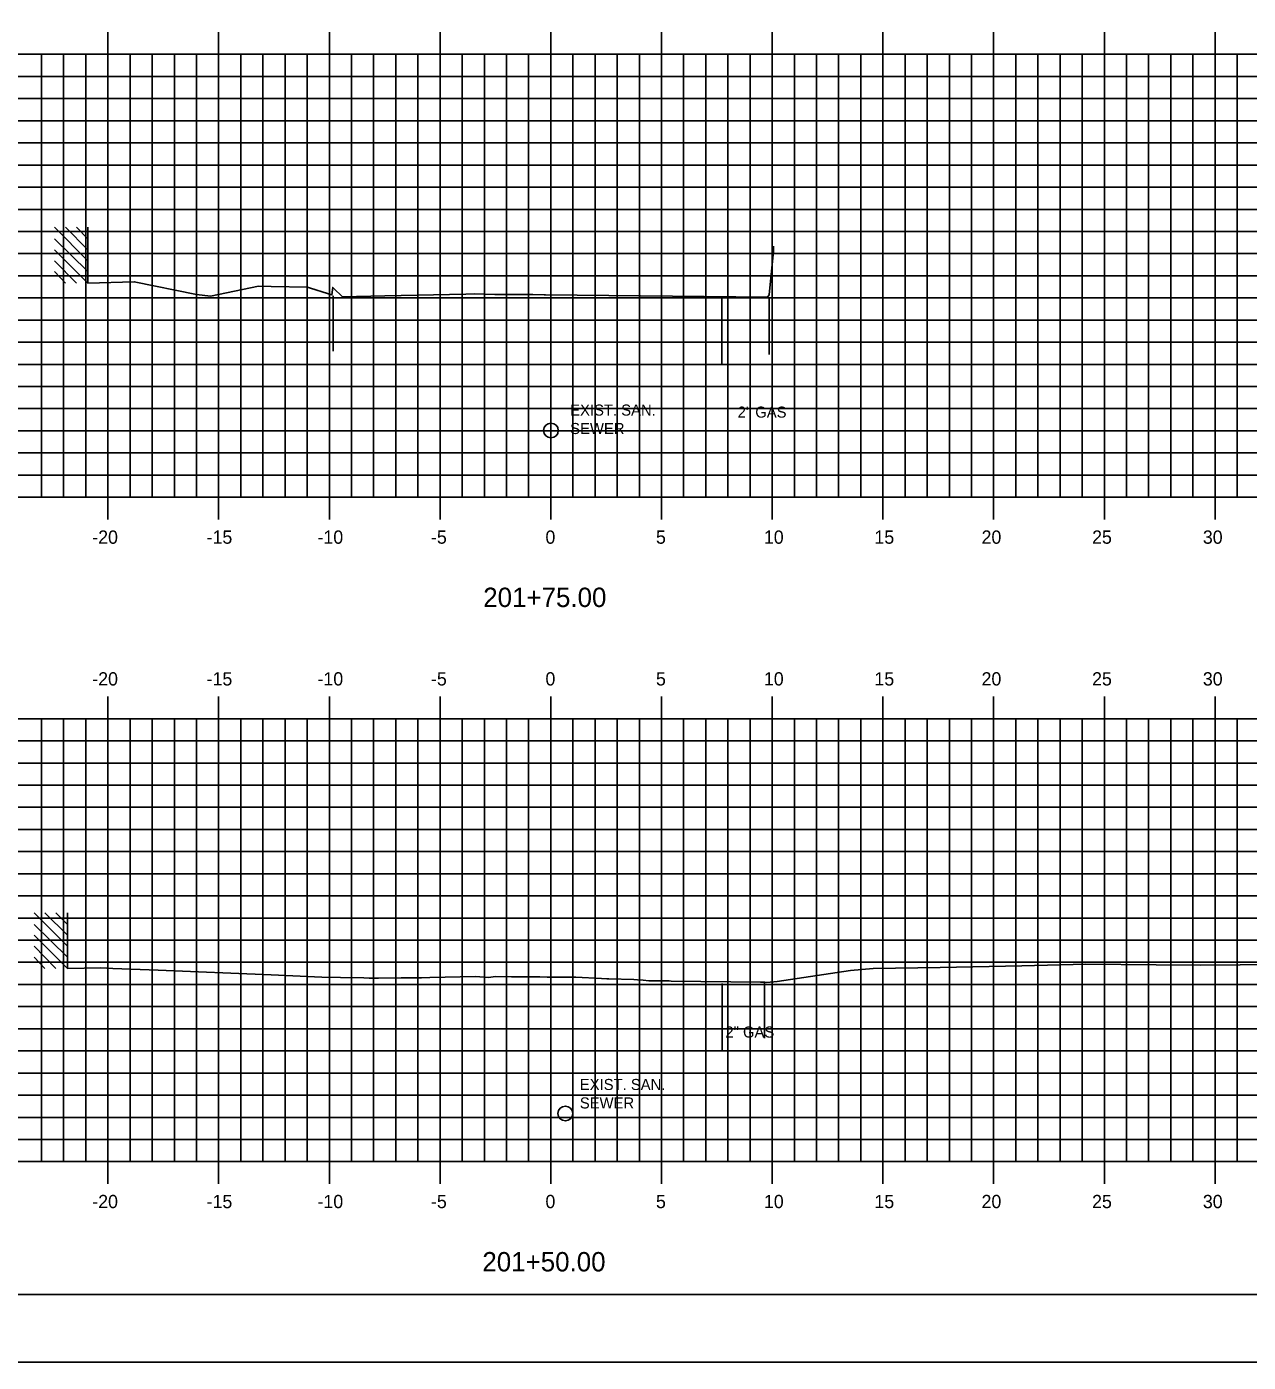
# Model space of a CAD drawing. Extents: x 1023905 to 1024075, y 394697 to 394807.
# Drawn here: x 1023964 to 1024019.2, y 394696.5 to 394756.9 of the extents above; entities that cross this region are included whole.
import ezdxf

# ---------------------------------------------------------------- set-up
doc = ezdxf.new("R2010")
doc.units = 0
for name, color, linetype in [('BORDER', 7, 'Continuous'), ('D_Text_Monospaced', 7, 'Continuous'), ('H_V ANNOTATION', 7, 'Continuous'), ('MAJOR', 7, 'Continuous'), ('MINOR', 7, 'Continuous'), ('PLOT BOUNDARY', 7, 'Continuous'), ('S_Buildings_SillElevation', 7, 'Continuous'), ('S_Roadway_Centerline', 7, 'Continuous'), ('S_Roadway_Edge_Pavement', 7, 'Continuous'), ('S_Utilities_UG_Gas_Line', 7, 'Continuous'), ('S_Utilities_UG_Sanitary_Sewer', 7, 'Continuous')]:
    doc.layers.add(name, color=color, linetype=linetype)

msp = doc.modelspace()

# ---------------------------------------------------------------- linework, layer by layer
at = {"layer": 'BORDER'}
msp.add_line((1023912.667, 394699.607), (1024072.667, 394699.607), dxfattribs=at)
at = {"layer": 'MAJOR'}
for p, q in [((1023967.667, 394756.609), (1023967.667, 394755.607)), ((1023972.667, 394756.609), (1023972.667, 394755.607)), ((1023977.667, 394756.609), (1023977.667, 394755.607)), ((1023982.667, 394756.609), (1023982.667, 394755.607)), ((1023987.667, 394756.609), (1023987.667, 394755.607)), ((1023992.667, 394756.609), (1023992.667, 394755.607)), ((1023997.667, 394756.609), (1023997.667, 394755.607)), ((1024002.667, 394756.609), (1024002.667, 394755.607)), ((1024007.667, 394756.609), (1024007.667, 394755.607)), ((1024012.667, 394756.609), (1024012.667, 394755.607)), ((1024017.667, 394756.609), (1024017.667, 394755.607)), ((1023917.667, 394755.607), (1024057.667, 394755.607)), ((1023967.667, 394735.607), (1023967.667, 394755.607)), ((1023972.667, 394735.607), (1023972.667, 394755.607)), ((1023977.667, 394735.607), (1023977.667, 394755.607)), ((1023982.667, 394735.607), (1023982.667, 394755.607)), ((1023987.667, 394735.607), (1023987.667, 394755.607)), ((1023992.667, 394735.607), (1023992.667, 394755.607)), ((1023997.667, 394735.607), (1023997.667, 394755.607)), ((1024002.667, 394735.607), (1024002.667, 394755.607)), ((1024007.667, 394735.607), (1024007.667, 394755.607)), ((1024012.667, 394735.607), (1024012.667, 394755.607)), ((1024017.667, 394735.607), (1024017.667, 394755.607)), ((1023917.667, 394750.607), (1024057.667, 394750.607)), ((1023917.667, 394745.607), (1024057.667, 394745.607)), ((1023917.667, 394740.607), (1024057.667, 394740.607)), ((1023917.667, 394735.607), (1024057.667, 394735.607)), ((1023967.667, 394734.605), (1023967.667, 394735.607)), ((1023972.667, 394734.605), (1023972.667, 394735.607)), ((1023977.667, 394734.605), (1023977.667, 394735.607)), ((1023982.667, 394734.605), (1023982.667, 394735.607)), ((1023987.667, 394734.605), (1023987.667, 394735.607)), ((1023992.667, 394734.605), (1023992.667, 394735.607)), ((1023997.667, 394734.605), (1023997.667, 394735.607)), ((1024002.667, 394734.605), (1024002.667, 394735.607)), ((1024007.667, 394734.605), (1024007.667, 394735.607)), ((1024012.667, 394734.605), (1024012.667, 394735.607)), ((1024017.667, 394734.605), (1024017.667, 394735.607)), ((1023967.667, 394726.609), (1023967.667, 394725.607)), ((1023972.667, 394726.609), (1023972.667, 394725.607)), ((1023977.667, 394726.609), (1023977.667, 394725.607)), ((1023982.667, 394726.609), (1023982.667, 394725.607)), ((1023987.667, 394726.609), (1023987.667, 394725.607)), ((1023992.667, 394726.609), (1023992.667, 394725.607)), ((1023997.667, 394726.609), (1023997.667, 394725.607)), ((1024002.667, 394726.609), (1024002.667, 394725.607)), ((1024007.667, 394726.609), (1024007.667, 394725.607)), ((1024012.667, 394726.609), (1024012.667, 394725.607)), ((1024017.667, 394726.609), (1024017.667, 394725.607)), ((1023917.667, 394725.607), (1024057.667, 394725.607)), ((1023967.667, 394705.607), (1023967.667, 394725.607)), ((1023972.667, 394705.607), (1023972.667, 394725.607)), ((1023977.667, 394705.607), (1023977.667, 394725.607)), ((1023982.667, 394705.607), (1023982.667, 394725.607)), ((1023987.667, 394705.607), (1023987.667, 394725.607)), ((1023992.667, 394705.607), (1023992.667, 394725.607)), ((1023997.667, 394705.607), (1023997.667, 394725.607)), ((1024002.667, 394705.607), (1024002.667, 394725.607)), ((1024007.667, 394705.607), (1024007.667, 394725.607)), ((1024012.667, 394705.607), (1024012.667, 394725.607)), ((1024017.667, 394705.607), (1024017.667, 394725.607)), ((1023917.667, 394720.607), (1024057.667, 394720.607)), ((1023917.667, 394715.607), (1024057.667, 394715.607)), ((1023917.667, 394710.607), (1024057.667, 394710.607)), ((1023917.667, 394705.607), (1024057.667, 394705.607)), ((1023967.667, 394704.605), (1023967.667, 394705.607)), ((1023972.667, 394704.605), (1023972.667, 394705.607)), ((1023977.667, 394704.605), (1023977.667, 394705.607)), ((1023982.667, 394704.605), (1023982.667, 394705.607)), ((1023987.667, 394704.605), (1023987.667, 394705.607)), ((1023992.667, 394704.605), (1023992.667, 394705.607)), ((1023997.667, 394704.605), (1023997.667, 394705.607)), ((1024002.667, 394704.605), (1024002.667, 394705.607)), ((1024007.667, 394704.605), (1024007.667, 394705.607)), ((1024012.667, 394704.605), (1024012.667, 394705.607)), ((1024017.667, 394704.605), (1024017.667, 394705.607))]:
    msp.add_line(p, q, dxfattribs=at)
at = {"layer": 'MINOR'}
for p, q in [((1023964.667, 394735.607), (1023964.667, 394755.607)), ((1023965.667, 394735.607), (1023965.667, 394755.607)), ((1023966.667, 394735.607), (1023966.667, 394755.607)), ((1023968.667, 394735.607), (1023968.667, 394755.607)), ((1023969.667, 394735.607), (1023969.667, 394755.607)), ((1023970.667, 394735.607), (1023970.667, 394755.607)), ((1023971.667, 394735.607), (1023971.667, 394755.607)), ((1023973.667, 394735.607), (1023973.667, 394755.607)), ((1023974.667, 394735.607), (1023974.667, 394755.607)), ((1023975.667, 394735.607), (1023975.667, 394755.607)), ((1023976.667, 394735.607), (1023976.667, 394755.607)), ((1023978.667, 394735.607), (1023978.667, 394755.607)), ((1023979.667, 394735.607), (1023979.667, 394755.607)), ((1023980.667, 394735.607), (1023980.667, 394755.607)), ((1023981.667, 394735.607), (1023981.667, 394755.607)), ((1023983.667, 394735.607), (1023983.667, 394755.607)), ((1023984.667, 394735.607), (1023984.667, 394755.607)), ((1023985.667, 394735.607), (1023985.667, 394755.607)), ((1023986.667, 394735.607), (1023986.667, 394755.607)), ((1023988.667, 394735.607), (1023988.667, 394755.607)), ((1023989.667, 394735.607), (1023989.667, 394755.607)), ((1023990.667, 394735.607), (1023990.667, 394755.607)), ((1023991.667, 394735.607), (1023991.667, 394755.607)), ((1023993.667, 394735.607), (1023993.667, 394755.607)), ((1023994.667, 394735.607), (1023994.667, 394755.607)), ((1023995.667, 394735.607), (1023995.667, 394755.607)), ((1023996.667, 394735.607), (1023996.667, 394755.607)), ((1023998.667, 394735.607), (1023998.667, 394755.607)), ((1023999.667, 394735.607), (1023999.667, 394755.607)), ((1024000.667, 394735.607), (1024000.667, 394755.607)), ((1024001.667, 394735.607), (1024001.667, 394755.607)), ((1024003.667, 394735.607), (1024003.667, 394755.607)), ((1024004.667, 394735.607), (1024004.667, 394755.607)), ((1024005.667, 394735.607), (1024005.667, 394755.607)), ((1024006.667, 394735.607), (1024006.667, 394755.607)), ((1024008.667, 394735.607), (1024008.667, 394755.607)), ((1024009.667, 394735.607), (1024009.667, 394755.607)), ((1024010.667, 394735.607), (1024010.667, 394755.607)), ((1024011.667, 394735.607), (1024011.667, 394755.607)), ((1024013.667, 394735.607), (1024013.667, 394755.607)), ((1024014.667, 394735.607), (1024014.667, 394755.607)), ((1024015.667, 394735.607), (1024015.667, 394755.607)), ((1024016.667, 394735.607), (1024016.667, 394755.607)), ((1024018.667, 394735.607), (1024018.667, 394755.607)), ((1023917.667, 394754.607), (1024057.667, 394754.607)), ((1023917.667, 394753.607), (1024057.667, 394753.607)), ((1023917.667, 394752.607), (1024057.667, 394752.607)), ((1023917.667, 394751.607), (1024057.667, 394751.607)), ((1023917.667, 394749.607), (1024057.667, 394749.607)), ((1023917.667, 394748.607), (1024057.667, 394748.607)), ((1023917.667, 394747.607), (1024057.667, 394747.607)), ((1023917.667, 394746.607), (1024057.667, 394746.607)), ((1023917.667, 394744.607), (1024057.667, 394744.607)), ((1023917.667, 394743.607), (1024057.667, 394743.607)), ((1023917.667, 394742.607), (1024057.667, 394742.607)), ((1023917.667, 394741.607), (1024057.667, 394741.607)), ((1023917.667, 394739.607), (1024057.667, 394739.607)), ((1023917.667, 394738.607), (1024057.667, 394738.607)), ((1023917.667, 394737.607), (1024057.667, 394737.607)), ((1023917.667, 394736.607), (1024057.667, 394736.607)), ((1023964.667, 394705.607), (1023964.667, 394725.607)), ((1023965.667, 394705.607), (1023965.667, 394725.607)), ((1023966.667, 394705.607), (1023966.667, 394725.607)), ((1023968.667, 394705.607), (1023968.667, 394725.607)), ((1023969.667, 394705.607), (1023969.667, 394725.607)), ((1023970.667, 394705.607), (1023970.667, 394725.607)), ((1023971.667, 394705.607), (1023971.667, 394725.607)), ((1023973.667, 394705.607), (1023973.667, 394725.607)), ((1023974.667, 394705.607), (1023974.667, 394725.607)), ((1023975.667, 394705.607), (1023975.667, 394725.607)), ((1023976.667, 394705.607), (1023976.667, 394725.607)), ((1023978.667, 394705.607), (1023978.667, 394725.607)), ((1023979.667, 394705.607), (1023979.667, 394725.607)), ((1023980.667, 394705.607), (1023980.667, 394725.607)), ((1023981.667, 394705.607), (1023981.667, 394725.607)), ((1023983.667, 394705.607), (1023983.667, 394725.607)), ((1023984.667, 394705.607), (1023984.667, 394725.607)), ((1023985.667, 394705.607), (1023985.667, 394725.607)), ((1023986.667, 394705.607), (1023986.667, 394725.607)), ((1023988.667, 394705.607), (1023988.667, 394725.607)), ((1023989.667, 394705.607), (1023989.667, 394725.607)), ((1023990.667, 394705.607), (1023990.667, 394725.607)), ((1023991.667, 394705.607), (1023991.667, 394725.607)), ((1023993.667, 394705.607), (1023993.667, 394725.607)), ((1023994.667, 394705.607), (1023994.667, 394725.607)), ((1023995.667, 394705.607), (1023995.667, 394725.607)), ((1023996.667, 394705.607), (1023996.667, 394725.607)), ((1023998.667, 394705.607), (1023998.667, 394725.607)), ((1023999.667, 394705.607), (1023999.667, 394725.607)), ((1024000.667, 394705.607), (1024000.667, 394725.607)), ((1024001.667, 394705.607), (1024001.667, 394725.607)), ((1024003.667, 394705.607), (1024003.667, 394725.607)), ((1024004.667, 394705.607), (1024004.667, 394725.607)), ((1024005.667, 394705.607), (1024005.667, 394725.607)), ((1024006.667, 394705.607), (1024006.667, 394725.607)), ((1024008.667, 394705.607), (1024008.667, 394725.607)), ((1024009.667, 394705.607), (1024009.667, 394725.607)), ((1024010.667, 394705.607), (1024010.667, 394725.607)), ((1024011.667, 394705.607), (1024011.667, 394725.607)), ((1024013.667, 394705.607), (1024013.667, 394725.607)), ((1024014.667, 394705.607), (1024014.667, 394725.607)), ((1024015.667, 394705.607), (1024015.667, 394725.607)), ((1024016.667, 394705.607), (1024016.667, 394725.607)), ((1024018.667, 394705.607), (1024018.667, 394725.607)), ((1023917.667, 394724.607), (1024057.667, 394724.607)), ((1023917.667, 394723.607), (1024057.667, 394723.607)), ((1023917.667, 394722.607), (1024057.667, 394722.607)), ((1023917.667, 394721.607), (1024057.667, 394721.607)), ((1023917.667, 394719.607), (1024057.667, 394719.607)), ((1023917.667, 394718.607), (1024057.667, 394718.607)), ((1023917.667, 394717.607), (1024057.667, 394717.607)), ((1023917.667, 394716.607), (1024057.667, 394716.607)), ((1023917.667, 394714.607), (1024057.667, 394714.607)), ((1023917.667, 394713.607), (1024057.667, 394713.607)), ((1023917.667, 394712.607), (1024057.667, 394712.607)), ((1023917.667, 394711.607), (1024057.667, 394711.607)), ((1023917.667, 394709.607), (1024057.667, 394709.607)), ((1023917.667, 394708.607), (1024057.667, 394708.607)), ((1023917.667, 394707.607), (1024057.667, 394707.607)), ((1023917.667, 394706.607), (1024057.667, 394706.607))]:
    msp.add_line(p, q, dxfattribs=at)
at = {"layer": 'PLOT BOUNDARY'}
msp.add_lwpolyline([(1023904.574, 394696.548), (1024074.574, 394696.548), (1024074.574, 394806.548), (1023904.574, 394806.548)], close=True, dxfattribs=at)
at = {"layer": 'S_Buildings_SillElevation'}
for p, q in [((1023966.767, 394746.289), (1023965.258, 394747.799)), ((1023966.767, 394745.797), (1023965.258, 394747.274)), ((1023966.767, 394746.782), (1023965.75, 394747.799)), ((1023966.767, 394747.274), (1023966.242, 394747.799)), ((1023966.767, 394745.272), (1023966.767, 394747.799)), ((1023966.767, 394745.272), (1023965.258, 394746.782)), ((1023966.242, 394745.272), (1023965.258, 394746.289)), ((1023965.75, 394745.272), (1023965.258, 394745.797)), ((1023965.841, 394715.338), (1023964.332, 394716.847)), ((1023965.841, 394715.83), (1023964.824, 394716.847)), ((1023965.841, 394716.322), (1023965.316, 394716.847)), ((1023965.841, 394714.321), (1023965.841, 394716.847)), ((1023965.841, 394714.846), (1023964.332, 394716.322)), ((1023965.841, 394714.321), (1023964.332, 394715.83)), ((1023965.316, 394714.321), (1023964.332, 394715.338)), ((1023964.824, 394714.321), (1023964.332, 394714.846))]:
    msp.add_line(p, q, dxfattribs=at)
at = {"layer": 'S_Roadway_Centerline'}
for points in [[(1023966.767, 394745.272), (1023968.859, 394745.34), (1023971.672, 394744.757), (1023972.295, 394744.692), (1023974.473, 394745.137), (1023975.043, 394745.127), (1023976.68, 394745.099), (1023976.817, 394745.055), (1023977.583, 394744.811), (1023977.736, 394744.762), (1023977.745, 394744.759), (1023977.785, 394744.746), (1023977.81, 394744.978), (1023977.821, 394745.082), (1023977.837, 394745.066), (1023977.85, 394745.054), (1023978.257, 394744.657), (1023980.174, 394744.698), (1023983.829, 394744.779), (1023984.205, 394744.788), (1023985.133, 394744.765), (1023986.855, 394744.755), (1023987.363, 394744.751), (1023987.426, 394744.749), (1023997.45, 394744.645), (1023997.528, 394744.753), (1023997.731, 394746.714), (1023997.731, 394746.943)], [(1023965.841, 394714.321), (1023967.353, 394714.351), (1023967.884, 394714.334), (1023969.938, 394714.255), (1023975.045, 394714.044), (1023977.323, 394713.938), (1023978.17, 394713.921), (1023979.223, 394713.907), (1023979.466, 394713.887), (1023979.823, 394713.898), (1023979.885, 394713.899), (1023980.917, 394713.91), (1023981.519, 394713.912), (1023981.825, 394713.905), (1023982.209, 394713.919), (1023984.266, 394713.961), (1023984.845, 394713.923), (1023985.192, 394713.96), (1023985.894, 394713.955), (1023987.174, 394713.945), (1023987.51, 394713.943), (1023988.261, 394713.938), (1023988.609, 394713.935), (1023988.799, 394713.932), (1023989.962, 394713.872), (1023990.205, 394713.86), (1023990.283, 394713.856), (1023991.416, 394713.826), (1023991.581, 394713.814), (1023991.837, 394713.796), (1023992.089, 394713.779), (1023992.401, 394713.775), (1023993.014, 394713.765), (1023993.101, 394713.764), (1023997.144, 394713.715), (1023997.315, 394713.71), (1023997.327, 394713.71), (1023997.419, 394713.7), (1023997.889, 394713.746), (1024001.195, 394714.233), (1024002.22, 394714.326), (1024005.252, 394714.381), (1024008.935, 394714.456), (1024011.83, 394714.52), (1024015.01, 394714.5), (1024016.998, 394714.484), (1024018.798, 394714.493), (1024023.914, 394714.505)]]:
    msp.add_lwpolyline(points, dxfattribs=at)
at = {"layer": 'S_Roadway_Edge_Pavement'}
for p, q in [((1023977.837, 394744.707), (1023977.837, 394742.207)), ((1023997.528, 394744.56), (1023997.528, 394742.06)), ((1023997.315, 394713.689), (1023997.315, 394711.189))]:
    msp.add_line(p, q, dxfattribs=at)
at = {"layer": 'S_Utilities_UG_Gas_Line'}
for p, q in [((1023995.394, 394744.572), (1023995.394, 394741.572)), ((1023995.41, 394713.647), (1023995.41, 394710.647))]:
    msp.add_line(p, q, dxfattribs=at)
at = {"layer": 'S_Utilities_UG_Sanitary_Sewer'}
for centre in [(1023987.674, 394738.62), (1023988.325, 394707.78)]:
    msp.add_circle(centre, 0.333, dxfattribs=at)

# ---------------------------------------------------------------- texts
at = {"layer": 'D_Text_Monospaced'}
for s, height, p in [('EXIST. SAN.', 0.49998, (1023988.544, 394739.294)), ('2" GAS', 0.5, (1023996.107, 394739.202)), ('SEWER', 0.5, (1023988.544, 394738.461)), ('2" GAS', 0.5, (1023995.553, 394711.21)), ('EXIST. SAN.', 0.49998, (1023988.979, 394708.842)), ('SEWER', 0.5, (1023988.979, 394708.008))]:
    msp.add_text(s, height=height, dxfattribs=at).set_placement(p)
at = {"layer": 'H_V ANNOTATION'}
for s, height, p in [('-20', 0.6, (1023966.96, 394733.507)), ('-15', 0.6, (1023972.124, 394733.507)), ('-10', 0.6, (1023977.132, 394733.507)), ('-5', 0.6, (1023982.257, 394733.507)), ('0', 0.6, (1023987.426, 394733.507)), ('5', 0.6, (1023992.418, 394733.507)), ('10', 0.6, (1023997.292, 394733.507)), ('15', 0.6, (1024002.284, 394733.507)), ('20', 0.6, (1024007.121, 394733.507)), ('25', 0.6, (1024012.113, 394733.507)), ('30', 0.6, (1024017.115, 394733.507)), ('201+75.00', 0.875, (1023984.616, 394730.65)), ('-20', 0.6, (1023966.96, 394727.107)), ('-15', 0.6, (1023972.124, 394727.107)), ('-10', 0.6, (1023977.132, 394727.107)), ('-5', 0.6, (1023982.257, 394727.107)), ('0', 0.6, (1023987.426, 394727.107)), ('5', 0.6, (1023992.418, 394727.107)), ('10', 0.6, (1023997.292, 394727.107)), ('15', 0.6, (1024002.284, 394727.107)), ('20', 0.6, (1024007.121, 394727.107)), ('25', 0.6, (1024012.113, 394727.107)), ('30', 0.6, (1024017.115, 394727.107)), ('-20', 0.6, (1023966.96, 394703.507)), ('-15', 0.6, (1023972.124, 394703.507)), ('-10', 0.6, (1023977.132, 394703.507)), ('-5', 0.6, (1023982.257, 394703.507)), ('0', 0.6, (1023987.426, 394703.507)), ('5', 0.6, (1023992.418, 394703.507)), ('10', 0.6, (1023997.292, 394703.507)), ('15', 0.6, (1024002.284, 394703.507)), ('20', 0.6, (1024007.121, 394703.507)), ('25', 0.6, (1024012.113, 394703.507)), ('30', 0.6, (1024017.115, 394703.507)), ('201+50.00', 0.875, (1023984.577, 394700.65))]:
    msp.add_text(s, height=height, dxfattribs=at).set_placement(p)
at = {"layer": 'S_Roadway_Centerline'}
for s, p in [('L', (1023987.355, 394744.82)), ('C', (1023987.358, 394744.828)), ('L', (1023987.502, 394713.927)), ('C', (1023987.505, 394713.934))]:
    msp.add_text(s, height=0.0146, dxfattribs=at).set_placement(p)

doc.saveas('drawing.dxf')
